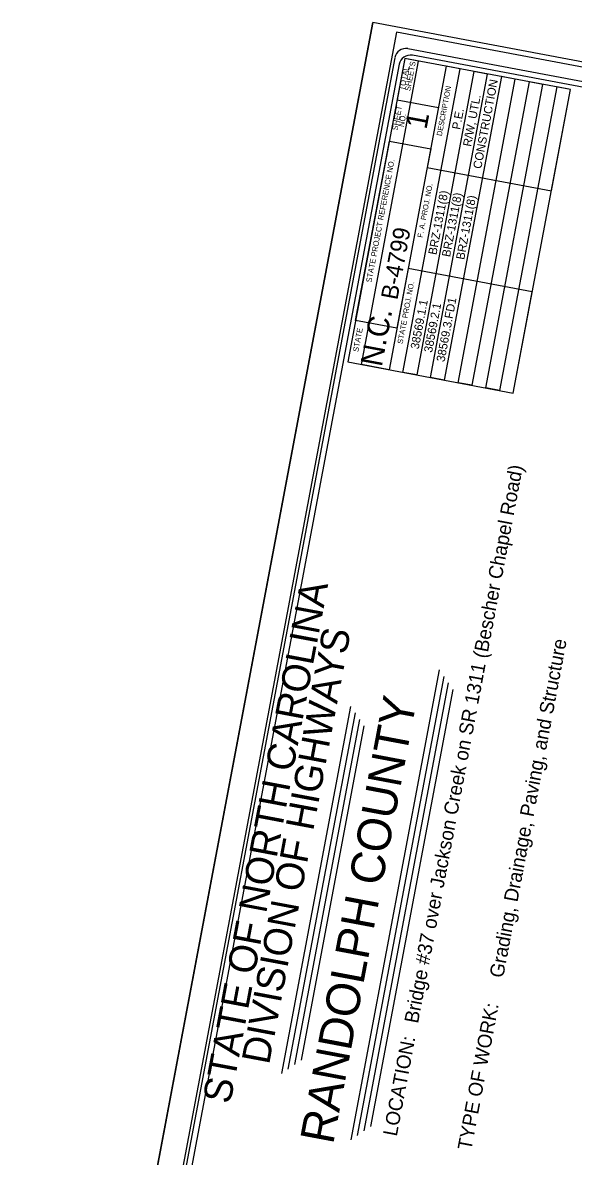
# Model space of a CAD drawing. Extents: x 1665923 to 1668724, y 690926 to 694920.
# Drawn here: x 1665923 to 1666413, y 691976 to 692985 of the extents above; entities that cross this region are included whole.
import ezdxf

# ---------------------------------------------------------------- set-up
doc = ezdxf.new("R2010")
doc.units = 0
for name, color, linetype in [('Sheet Cutting Line CELL', 7, 'Continuous'), ('Sheet Data Field CELL', 7, 'Continuous'), ('Sheet Plot Border Inside CELL', 7, 'Continuous'), ('Sheet Plot Border Outside CELL', 7, 'Continuous'), ('Sheet Title CELL', 7, 'Continuous'), ('Sheet Title Data Points CELL', 7, 'Continuous')]:
    doc.layers.add(name, color=color, linetype=linetype)

msp = doc.modelspace()

# ---------------------------------------------------------------- linework, layer by layer
at = {"layer": 'Sheet Cutting Line CELL'}
msp.add_line((1665922.7, 691330.5), (1666234.3, 692985.4), dxfattribs=at)
at = {"layer": 'Sheet Plot Border Inside CELL'}
msp.add_lwpolyline([(1666984, 691143.8), (1667292.4, 692781.5), (1666255.6, 692976.8), (1665947.1, 691339.1)], close=True, dxfattribs=at)
at = {"layer": 'Sheet Plot Border Outside CELL'}
msp.add_lwpolyline([(1666234.3, 692985.4), (1665922.7, 691330.5), (1667003.6, 691126.9), (1667315.3, 692781.8)], close=True, dxfattribs=at)
at = {"layer": 'Sheet Title CELL'}
for p, q in [((1666215, 691990.5), (1666293.9, 692409.1)), ((1666220.8, 691994.5), (1666297.9, 692403.3)), ((1666226.7, 691998.5), (1666301.8, 692397.5)), ((1666232.5, 692002.5), (1666305.8, 692391.6)), ((1666153.3, 692049.6), (1666214.9, 692376.6)), ((1666159.1, 692053.6), (1666218.9, 692370.8)), ((1666165, 692057.6), (1666222.8, 692364.9)), ((1666170.8, 692061.6), (1666226.8, 692359.1))]:
    msp.add_line(p, q, dxfattribs=at)
for points in [[(1666253.9, 692954.2), (1665980, 691499.8)], [(1667277.8, 692771.5), (1666265.6, 692962.2)], [(1667090.2, 692801.8), (1666269.6, 692956.4)], [(1666257.9, 692948.4), (1665995.1, 691552.9)], [(1666359.4, 692655.5), (1666410.3, 692925.8), (1666398.1, 692928.1), (1666347.2, 692657.8), (1666334.9, 692660.1), (1666385.8, 692930.4), (1666373.5, 692932.7), (1666322.6, 692662.5), (1666310.3, 692664.8), (1666361.2, 692935), (1666348.9, 692937.3), (1666298, 692667.1), (1666285.7, 692669.4), (1666336.6, 692939.6), (1666324.4, 692942), (1666273.5, 692671.7), (1666261.2, 692674), (1666312.1, 692944.3), (1666299.8, 692946.6), (1666248.9, 692676.3), (1666224.3, 692681), (1666275.2, 692951.2), (1666262.9, 692953.5), (1666212, 692683.3), (1666359.4, 692655.5), (1666376.4, 692745.6), (1666265.9, 692766.4), (1666255.8, 692713.2), (1666219, 692720.1), (1666249.1, 692879.8), (1666285.9, 692872.9), (1666282.8, 692856.5), (1666393.4, 692835.7), (1666410.3, 692925.8), (1666262.9, 692953.5), (1666256, 692916.7), (1666292.8, 692909.7)]]:
    msp.add_lwpolyline(points, dxfattribs=at)
for centre in [(1666263.7, 692952.4), (1666267.7, 692946.5)]:
    msp.add_arc(centre, 10, 79.3338, 169.3338, dxfattribs=at)
at = {"layer": 'Sheet Title Data Points CELL'}
for p, q in [((1666315.7, 692312), (1666315.7, 692312)), ((1666240.1, 692204.1), (1666240.1, 692204.1))]:
    msp.add_line(p, q, dxfattribs=at)

# ---------------------------------------------------------------- texts
at = {"layer": 'Sheet Data Field CELL'}
for s, height, p in [('CONSTRUCTION', 7.5, (1666330.9, 692854.8)), ('R/W, UTL.', 7.5, (1666321.9, 692874.6)), ('P.E.      ', 7.5, (1666312.1, 692889.7)), ('BRZ-1311(8)   ', 7.5, (1666291, 692778.2)), ('BRZ-1311(8)   ', 7.5, (1666303.1, 692776.3)), ('BRZ-1311(8)   ', 7.5, (1666315.7, 692773.9)), ('B-4799    ', 15, (1666256.2, 692737.9)), ('38569.1.1 ', 7.5, (1666275.2, 692694.2)), ('38569.2.1 ', 7.5, (1666287.1, 692691.2)), ('38569.3.FD1 ', 7.5, (1666298.2, 692682.9)), ('Bridge #37 over Jackson Creek on SR 1311 (Bescher Chapel Road)', 12.5, (1666274.6, 692093.7)), ('Grading, Drainage, Paving, and Structure', 12.5, (1666350.4, 692134.2)), ('RANDOLPH COUNTY', 30, (1666199, 691985.8))]:
    msp.add_text(s, height=height, rotation=79.3338, dxfattribs=at).set_placement(p)
at = {"layer": 'Sheet Title CELL'}
for s, height, p in [('TOTAL', 5, (1666262.7, 692924.7)), ('SHEETS', 5, (1666267.7, 692924.1)), ('DESCRIPTION', 4.8, (1666295.8, 692884.1)), ('SHEET', 5, (1666256.4, 692889.1)), ('NO.', 5, (1666262, 692892.2)), ('1', 19.4, (1666282.1, 692889.7)), ('STATE PROJECT REFERENCE NO.', 5, (1666233.2, 692753.7)), ('F. A. PROJ. NO.', 4.8, (1666278.7, 692793.6)), ('STATE PROJ. NO.', 4.8, (1666260.9, 692699)), ('N.C.', 19.35, (1666242.3, 692678.3)), ('STATE', 5, (1666221.5, 692691.9)), ('STATE OF NORTH CAROLINA', 25, (1666107.4, 692021.8)), ('DIVISION OF HIGHWAYS', 25, (1666142, 692056.9)), ('TYPE OF WORK:', 12.5, (1666322, 691980.7)), ('LOCATION: ', 12.5, (1666255.7, 691993.2))]:
    msp.add_text(s, height=height, rotation=79.3338, dxfattribs=at).set_placement(p)

doc.saveas('drawing.dxf')
